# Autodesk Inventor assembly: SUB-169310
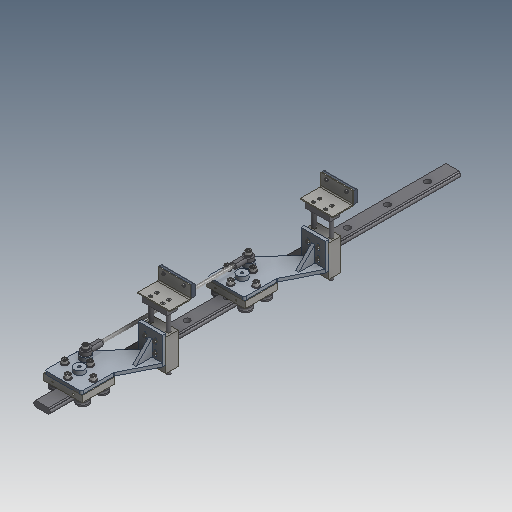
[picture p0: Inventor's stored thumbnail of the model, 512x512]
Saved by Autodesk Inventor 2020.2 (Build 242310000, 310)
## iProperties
Created: 2000-01
Part Number: SUB-169310
Document SubType Name: Assembly
Designer: sspink
Mass: 15907.3 g
Surface Area: 7038.83 cm^2
Volume: 3183.15 cm^3
Density: 4.99736 g/cm^3
Control State: 0
Master: False
Checked Out: False
Shininess: 0.0
Length Units: 11269
Angle Units: 11279
Time Units: 11290
Mass Units: 11283
Length Display Precision: 3
Angle Display Precision: 2
Compacted: True
Dimensions: 234,7x1280x185,8 mm
Mass: 15,907 kg
DocNumber: SUB-169310.iam
Folder: 01 - Themengebiete\Simplification\01 - Packaging machine\
VDS_Category: 3D Komponenten
Density: 0.0
Volumn: 0.0
Area: 0.0
PropertySet Name: Model Information
Author: sspink
Revision Number: -
Title: SUB-169310
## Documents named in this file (17)
- D:\07 - DEMODATEN\OTX 2019 - Dataset - UPDATE - Dez2019\Designs\07-Packing machine\SUB-169310.iam
- D:\07 - DEMODATEN\OTX 2019 - Dataset - UPDATE - Dez2019\Designs\07-Packing machine\Parts\ADSK-011800.ipt
- D:\07 - DEMODATEN\OTX 2019 - Dataset - UPDATE - Dez2019\Designs\07-Packing machine\A105014.iam
- D:\07 - DEMODATEN\OTX 2019 - Dataset - UPDATE - Dez2019\Designs\07-Packing machine\500410R.iam
- D:\07 - DEMODATEN\OTX 2019 - Dataset - UPDATE - Dez2019\Designs\07-Packing machine\Parts\ADSK-011398.ipt
- D:\07 - DEMODATEN\OTX 2019 - Dataset - UPDATE - Dez2019\Designs\07-Packing machine\A105047.iam
- D:\07 - DEMODATEN\OTX 2019 - Dataset - UPDATE - Dez2019\Designs\07-Packing machine\Parts\ADSK-011478.ipt
- D:\07 - DEMODATEN\OTX 2019 - Dataset - UPDATE - Dez2019\Designs\07-Packing machine\A103970.iam
- D:\07 - DEMODATEN\OTX 2019 - Dataset - UPDATE - Dez2019\Designs\07-Packing machine\Parts\ADSK-011393.ipt
- D:\07 - DEMODATEN\OTX 2019 - Dataset - UPDATE - Dez2019\Content Center Files\de-DE\DIN 125-1  B\DIN 125-1 - B 10,5.ipt
- D:\07 - DEMODATEN\OTX 2019 - Dataset - UPDATE - Dez2019\Content Center Files\de-DE\ISO 4762(2)\ISO 4762 - M10 x 25ISO.ipt
- D:\07 - DEMODATEN\OTX 2019 - Dataset - UPDATE - Dez2019\Content Center Files\de-DE\ISO 10642(1)\ISO 10642 - M5x12.ipt
- D:\07 - DEMODATEN\OTX 2019 - Dataset - UPDATE - Dez2019\Content Center Files\de-DE\DIN 125-1  B\DIN 125-1 - B 5,3.ipt
- D:\07 - DEMODATEN\OTX 2019 - Dataset - UPDATE - Dez2019\Content Center Files\de-DE\ISO 4032(1)\ISO 4032 - M5DIN EN.ipt
- D:\07 - DEMODATEN\OTX 2019 - Dataset - UPDATE - Dez2019\Content Center Files\de-DE\ISO 4762(2)\ISO 4762 - M5 x 50ISO.ipt
- D:\07 - DEMODATEN\OTX 2019 - Dataset - UPDATE - Dez2019\Content Center Files\de-DE\DIN 125-1  B\DIN 125-1 - B 4,3.ipt
- D:\07 - DEMODATEN\OTX 2019 - Dataset - UPDATE - Dez2019\Content Center Files\de-DE\ISO 4762(2)\ISO 4762 - M4 x 10ISO.ipt
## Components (74 placed, 16 different names)
1. ADSK-011800:1 — Flush:3, Flush:4, Mate:5, Mate:6, Mate:10, Mate:11, STROKE
2. A105014:1 [sub-assembly] — STROKE, Mate:1, Flush:1, Mate:2, Mate:5, Mate:6, Flush:9
3. 500410R:1 [sub-assembly] — Mate:1, Flush:1, Flush:2, Mate:2, Mate:3, Flush:6, Einfügen:8, Passend:66, Passend:68, Passend:70, Passend:72
4. A103970:1 [sub-assembly] — Flush:2, Mate:3, Flush:6, Insert:2, Insert:3, Passend:24, Passend:25, Passend:26
5. ADSK-011393:1 — Insert:2, Insert:3, Insert:4, Insert:5, Passend:24, Passend:25, Passend:26, Passend:81, Passend:83
6. 500410R:2 [sub-assembly] — Mate:7, Flush:5, Flush:7, Mate:8, Mate:9, Flush:8, Einfügen:9, Passend:58, Passend:60, Passend:62, Passend:64
7. A105014:2 [sub-assembly] — Mate:8, Mate:9, Flush:8, Mate:10, Mate:11, Flush:9
8. A103970:2 [sub-assembly] — Mate:7, Flush:5, Flush:7, Insert:6, Insert:7, Passend:21, Passend:22, Passend:23
9. ADSK-011393:2 — Insert:6, Insert:7, Passend:21, Passend:22, Passend:23, Passend:73, Passend:74, Passend:75, Passend:77, Passend:79
10. A105047:1 [sub-assembly] — Passend:18, Einfügen:9, Passend:20, Passend:30
11. A105047:2 [sub-assembly] — Einfügen:8, Passend:19, Passend:28
12. ADSK-011398:1 — Passend:18, Passend:19, Passend:20
13. ADSK-011478:1 — Insert:4, Insert:5
14. ADSK-011478:2 — Passend:73, Passend:74, Passend:75
15. DIN 125-1 B B 4,3:1 — Passend:77
16. DIN 125-1 B B 4,3:2 — Passend:79
17. DIN 125-1 B B 4,3:3 — Passend:81
18. DIN 125-1 B B 4,3:4 — Passend:83
19. ISO 4762 M4 x 10:1
20. ISO 4762 M4 x 10:2
21. ISO 4762 M4 x 10:3
22. ISO 4762 M4 x 10:4
23. DIN 125-1 B B 10,5:1 — Passend:28
24. DIN 125-1 B B 10,5:2 — Passend:30, Passend:32
25. ISO 4762 M10 x 25:1 — Passend:32
26. ISO 4762 M10 x 25:2
27. DIN 125-1 B B 10,5:3 — Passend:42, Passend:44, Passend:46, Passend:48
28. DIN 125-1 B B 10,5:4
29. DIN 125-1 B B 10,5:5
30. DIN 125-1 B B 10,5:6
31. DIN 125-1 B B 10,5:7 — Passend:34, Passend:36, Passend:38, Passend:40
32. DIN 125-1 B B 10,5:8
33. DIN 125-1 B B 10,5:9
34. DIN 125-1 B B 10,5:10
35. ISO 4762 M10 x 25:3 — Passend:34
36. ISO 4762 M10 x 25:4 — Passend:36
37. ISO 4762 M10 x 25:5 — Passend:38
38. ISO 4762 M10 x 25:6 — Passend:40
39. ISO 4762 M10 x 25:7 — Passend:42
40. ISO 4762 M10 x 25:8 — Passend:44
41. ISO 4762 M10 x 25:9 — Passend:46
42. ISO 4762 M10 x 25:10 — Passend:48
43. ISO 10642 M5x12:1
44. ISO 10642 M5x12:2
45. ISO 10642 M5x12:3
46. ISO 10642 M5x12:4
47. ISO 10642 M5x12:5
48. ISO 10642 M5x12:6
49. ISO 10642 M5x12:7
50. ISO 10642 M5x12:8
51. DIN 125-1 B B 5,3:1 — Passend:58
52. DIN 125-1 B B 5,3:2 — Passend:60
53. DIN 125-1 B B 5,3:3 — Passend:62
54. DIN 125-1 B B 5,3:4 — Passend:64
55. DIN EN 24032 M5:1
56. DIN EN 24032 M5:2
57. DIN EN 24032 M5:3
58. DIN EN 24032 M5:4
59. ISO 4762 M5 x 50:1
60. ISO 4762 M5 x 50:2
61. ISO 4762 M5 x 50:3
62. ISO 4762 M5 x 50:4
63. DIN 125-1 B B 5,3:5 — Passend:66
64. DIN 125-1 B B 5,3:6 — Passend:68
65. DIN 125-1 B B 5,3:7 — Passend:70
66. DIN 125-1 B B 5,3:8 — Passend:72
67. DIN EN 24032 M5:5
68. DIN EN 24032 M5:6
69. DIN EN 24032 M5:7
70. DIN EN 24032 M5:8
71. ISO 4762 M5 x 50:5
72. ISO 4762 M5 x 50:6
73. ISO 4762 M5 x 50:7
74. ISO 4762 M5 x 50:8
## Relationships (63: Mate 45, Flush 10, Insert 8)
- STROKE [Flush]: ADSK-011800:1 ↔ A105014:1
- Mate:1: A105014:1 ↔ 500410R:1
- Flush:1: A105014:1 ↔ 500410R:1
- Flush:2: 500410R:1 ↔ A103970:1
- Mate:2: A105014:1 ↔ 500410R:1
- Mate:3: 500410R:1 ↔ A103970:1
- Flush:3: ADSK-011800:1
- Flush:4: ADSK-011800:1
- Mate:5: ADSK-011800:1 ↔ A105014:1
- Mate:6: ADSK-011800:1 ↔ A105014:1
- Mate:7: 500410R:2 ↔ A103970:2
- Flush:5: 500410R:2 ↔ A103970:2
- Flush:6: 500410R:1 ↔ A103970:1
- Flush:7: 500410R:2 ↔ A103970:2
- Mate:8: 500410R:2 ↔ A105014:2
- Mate:9: 500410R:2 ↔ A105014:2
- Flush:8: 500410R:2 ↔ A105014:2
- Mate:10: ADSK-011800:1 ↔ A105014:2
- Mate:11: ADSK-011800:1 ↔ A105014:2
- Flush:9: A105014:1 ↔ A105014:2
- Insert:2: A103970:1 ↔ ADSK-011393:1
- Insert:3: A103970:1 ↔ ADSK-011393:1
- Insert:4: ADSK-011393:1 ↔ ADSK-011478:1
- Insert:5: ADSK-011393:1 ↔ ADSK-011478:1
- Insert:6: A103970:2 ↔ ADSK-011393:2
- Insert:7: A103970:2 ↔ ADSK-011393:2
- Passend:18 [Mate]: A105047:1 ↔ ADSK-011398:1
- Einfügen:8 [Insert]: 500410R:1 ↔ A105047:2
- Einfügen:9 [Insert]: 500410R:2 ↔ A105047:1
- Passend:19 [Mate]: A105047:2 ↔ ADSK-011398:1
- Passend:20 [Mate]: A105047:1 ↔ ADSK-011398:1
- Passend:21 [Mate]: A103970:2 ↔ ADSK-011393:2
- Passend:22 [Mate]: A103970:2 ↔ ADSK-011393:2
- Passend:23 [Mate]: A103970:2 ↔ ADSK-011393:2
- Passend:24 [Mate]: A103970:1 ↔ ADSK-011393:1
- Passend:25 [Mate]: A103970:1 ↔ ADSK-011393:1
- Passend:26 [Mate]: A103970:1 ↔ ADSK-011393:1
- Passend:28 [Mate]: A105047:2 ↔ DIN 125-1 B B 10,5:1
- Passend:30 [Mate]: A105047:1 ↔ DIN 125-1 B B 10,5:2
- Passend:32 [Mate]: DIN 125-1 B B 10,5:2 ↔ ISO 4762 M10 x 25:1
- Passend:34 [Mate]: DIN 125-1 B B 10,5:7 ↔ ISO 4762 M10 x 25:3
- Passend:36 [Mate]: DIN 125-1 B B 10,5:7 ↔ ISO 4762 M10 x 25:4
- Passend:38 [Mate]: DIN 125-1 B B 10,5:7 ↔ ISO 4762 M10 x 25:5
- Passend:40 [Mate]: DIN 125-1 B B 10,5:7 ↔ ISO 4762 M10 x 25:6
- Passend:42 [Mate]: DIN 125-1 B B 10,5:3 ↔ ISO 4762 M10 x 25:7
- Passend:44 [Mate]: DIN 125-1 B B 10,5:3 ↔ ISO 4762 M10 x 25:8
- Passend:46 [Mate]: DIN 125-1 B B 10,5:3 ↔ ISO 4762 M10 x 25:9
- Passend:48 [Mate]: DIN 125-1 B B 10,5:3 ↔ ISO 4762 M10 x 25:10
- Passend:58 [Mate]: 500410R:2 ↔ DIN 125-1 B B 5,3:1
- Passend:60 [Mate]: 500410R:2 ↔ DIN 125-1 B B 5,3:2
- Passend:62 [Mate]: 500410R:2 ↔ DIN 125-1 B B 5,3:3
- Passend:64 [Mate]: 500410R:2 ↔ DIN 125-1 B B 5,3:4
- Passend:66 [Mate]: 500410R:1 ↔ DIN 125-1 B B 5,3:5
- Passend:68 [Mate]: 500410R:1 ↔ DIN 125-1 B B 5,3:6
- Passend:70 [Mate]: 500410R:1 ↔ DIN 125-1 B B 5,3:7
- Passend:72 [Mate]: 500410R:1 ↔ DIN 125-1 B B 5,3:8
- Passend:73 [Mate]: ADSK-011393:2 ↔ ADSK-011478:2
- Passend:74 [Mate]: ADSK-011393:2 ↔ ADSK-011478:2
- Passend:75 [Mate]: ADSK-011393:2 ↔ ADSK-011478:2
- Passend:77 [Mate]: ADSK-011393:2 ↔ DIN 125-1 B B 4,3:1
- Passend:79 [Mate]: ADSK-011393:2 ↔ DIN 125-1 B B 4,3:2
- Passend:81 [Mate]: ADSK-011393:1 ↔ DIN 125-1 B B 4,3:3
- Passend:83 [Mate]: ADSK-011393:1 ↔ DIN 125-1 B B 4,3:4
